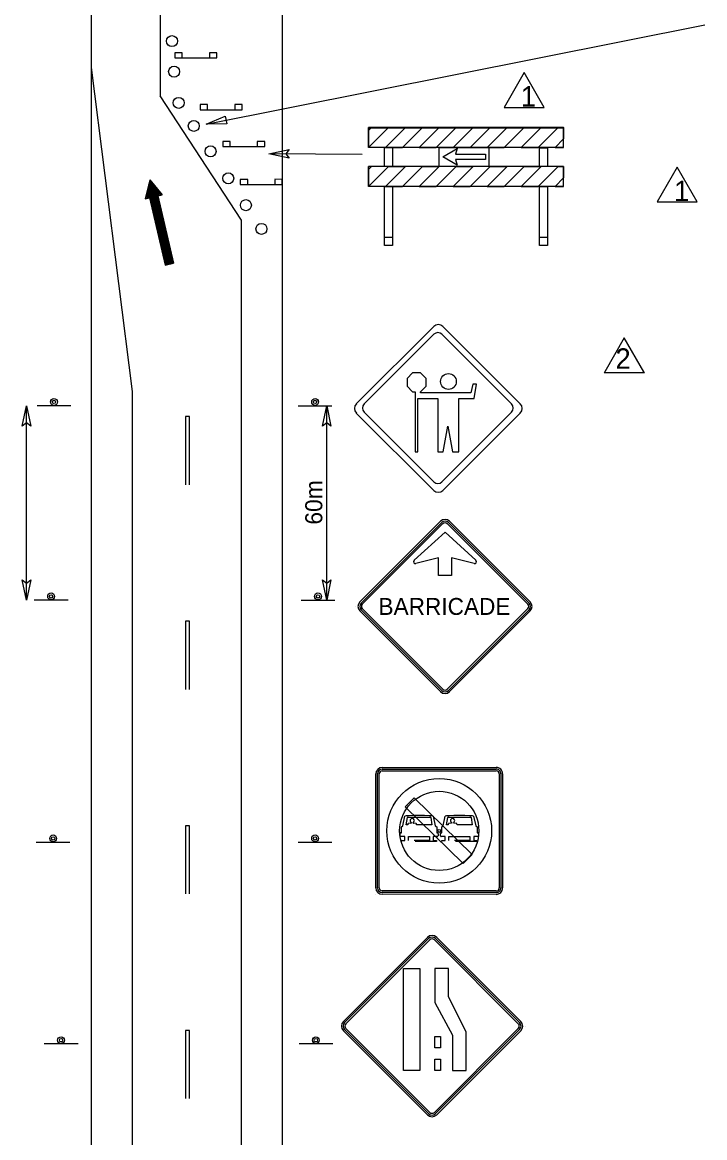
# Model space of a CAD drawing. Extents: x 1056 to 1280, y 240 to 519.
# Drawn here: x 1109.1 to 1157.5, y 308.9 to 388 of the extents above; entities that cross this region are included whole.
import ezdxf

# ---------------------------------------------------------------- set-up
doc = ezdxf.new("R2010")
doc.units = 0
for name, color, linetype in [('Level 1', 7, 'Continuous'), ('Level 10', 7, 'Continuous'), ('Level 17', 7, 'Continuous'), ('Level 29', 7, 'Continuous'), ('Level 44', 7, 'Continuous'), ('Level 5', 7, 'Continuous'), ('Level 60', 7, 'Continuous')]:
    doc.layers.add(name, color=color, linetype=linetype)

# ---------------------------------------------------------------- blocks, each defined once
blk = doc.blocks.new('LT1')
at = {"layer": 'Level 5'}
blk.add_lwpolyline([(0, 0), (-3, -0.62), (-2.504, 0), (-3, 0.62)], close=True, dxfattribs=at)

msp = doc.modelspace()

# ---------------------------------------------------------------- linework, layer by layer
at = {"layer": 'Level 1'}
for p, q in [((1136.814, 363.179), (1136.42, 362.785)), ((1137.371, 363.179), (1136.814, 363.179)), ((1137.765, 362.785), (1137.371, 363.179)), ((1136.42, 362.785), (1136.42, 362.228)), ((1137.765, 362.228), (1137.765, 362.785)), ((1141.085, 362.36), (1140.941, 361.761)), ((1141.335, 362.36), (1141.085, 362.36)), ((1141.172, 361.359), (1141.335, 362.36)), ((1136.42, 362.228), (1136.814, 361.834)), ((1136.814, 361.834), (1136.992, 361.834)), ((1136.992, 361.834), (1136.992, 357.568)), ((1137.371, 361.834), (1137.765, 362.228)), ((1137.371, 361.761), (1137.371, 361.834)), ((1140.941, 361.761), (1137.371, 361.761)), ((1137.188, 357.568), (1137.188, 361.359)), ((1137.188, 361.359), (1138.608, 361.359)), ((1138.608, 361.359), (1138.608, 357.568)), ((1140.096, 357.568), (1140.096, 361.359)), ((1140.096, 361.359), (1141.172, 361.359)), ((1138.984, 357.568), (1139.321, 359.384)), ((1139.321, 359.384), (1139.638, 357.568)), ((1136.992, 357.568), (1137.188, 357.568)), ((1138.608, 357.568), (1138.984, 357.568)), ((1139.638, 357.568), (1140.096, 357.568))]:
    msp.add_line(p, q, dxfattribs=at)
msp.add_circle((1139.357, 362.56), 0.559, dxfattribs=at)
at = {"layer": 'Level 10'}
for p, q in [((1114.044, 384.845), (1114.044, 432.01)), ((1127.591, 329.087), (1127.591, 431.499)), ((1114.044, 384.845), (1114.044, 397.84)), ((1122.169, 380.825), (1157.533, 387.859)), ((1116.947, 361.854), (1114.044, 384.845)), ((1114.044, 303.068), (1114.044, 384.845)), ((1124.688, 374.012), (1118.903, 382.817)), ((1118.173, 376.861), (1117.851, 375.527)), ((1118.133, 376.694), (1119.479, 370.866)), ((1118.173, 376.861), (1119.553, 370.883)), ((1118.173, 376.861), (1119.046, 375.803)), ((1118.281, 376.728), (1119.627, 370.9)), ((1117.93, 375.861), (1118, 375.561)), ((1117.971, 376.027), (1118.075, 375.579)), ((1118.012, 376.194), (1119.254, 370.814)), ((1118.052, 376.36), (1119.328, 370.831)), ((1118.091, 376.527), (1119.402, 370.848)), ((1118.391, 376.596), (1119.702, 370.917)), ((1118.5, 376.463), (1119.777, 370.934)), ((1118.609, 376.332), (1119.851, 370.952)), ((1118.718, 376.2), (1118.822, 375.751)), ((1118.827, 376.068), (1118.897, 375.768)), ((1118.937, 375.935), (1118.972, 375.786)), ((1117.851, 375.527), (1118.15, 375.596)), ((1117.891, 375.693), (1117.926, 375.545)), ((1118.15, 375.596), (1119.254, 370.814)), ((1118.747, 375.735), (1119.046, 375.803)), ((1118.747, 375.735), (1119.851, 370.952)), ((1124.688, 303.086), (1124.688, 374.012)), ((1119.254, 370.814), (1119.851, 370.952)), ((1116.947, 303.073), (1116.947, 361.854)), ((1109.429, 347.05), (1109.429, 360.84)), ((1130.722, 347.05), (1130.722, 360.84)), ((1120.705, 360.074), (1120.705, 355.236)), ((1120.995, 360.074), (1120.705, 360.074)), ((1120.995, 355.236), (1120.995, 360.074)), ((1120.705, 345.56), (1120.705, 340.722)), ((1120.995, 345.56), (1120.705, 345.56)), ((1120.995, 340.722), (1120.995, 345.56)), ((1120.705, 331.046), (1120.705, 326.208)), ((1120.995, 331.046), (1120.705, 331.046)), ((1120.995, 326.208), (1120.995, 331.046)), ((1127.591, 253.496), (1127.591, 329.087)), ((1120.705, 316.532), (1120.705, 311.694)), ((1120.995, 316.532), (1120.705, 316.532)), ((1120.995, 311.694), (1120.995, 316.532))]:
    msp.add_line(p, q, dxfattribs=at)
msp.add_lwpolyline([(1123.634, 380.841), (1122.169, 380.825), (1123.529, 381.371)], close=True, dxfattribs=at)
at = {"layer": 'Level 17'}
for p, q in [((1133.073, 346.927), (1138.792, 352.646)), ((1133.158, 346.842), (1138.877, 352.562)), ((1133.243, 346.758), (1138.962, 352.477)), ((1139.267, 352.477), (1144.987, 346.758)), ((1139.352, 352.562), (1145.071, 346.842)), ((1139.437, 352.646), (1145.156, 346.927)), ((1137.051, 349.644), (1137.051, 349.644)), ((1137.051, 349.644), (1137.051, 349.644)), ((1137.051, 349.644), (1137.051, 349.644)), ((1132.751, 346.605), (1132.751, 346.605)), ((1138.792, 340.563), (1133.073, 346.282)), ((1138.877, 340.648), (1133.158, 346.367)), ((1138.962, 340.733), (1133.243, 346.452)), ((1144.987, 346.452), (1139.267, 340.733)), ((1145.071, 346.367), (1139.352, 340.648)), ((1145.156, 346.282), (1139.437, 340.563)), ((1134.202, 326.645), (1134.202, 334.724)), ((1134.322, 326.645), (1134.322, 334.724)), ((1134.442, 326.645), (1134.442, 334.724)), ((1134.659, 335.181), (1142.743, 335.185)), ((1134.659, 335.061), (1142.743, 335.065)), ((1134.659, 334.941), (1142.743, 334.946)), ((1142.961, 334.729), (1142.96, 326.639)), ((1143.081, 334.729), (1143.08, 326.639)), ((1143.201, 334.729), (1143.2, 326.639)), ((1136.117, 331.041), (1136.267, 331.723)), ((1136.359, 331.104), (1136.445, 331.627)), ((1136.484, 331.667), (1138.053, 331.667)), ((1138.1, 331.627), (1138.18, 331.104)), ((1138.272, 331.723), (1138.422, 331.041)), ((1138.983, 331.041), (1139.133, 331.723)), ((1139.225, 331.104), (1139.311, 331.627)), ((1139.35, 331.667), (1140.919, 331.667)), ((1140.965, 331.627), (1141.046, 331.104)), ((1141.138, 331.723), (1141.288, 331.041)), ((1136.015, 330.971), (1136.118, 331.041)), ((1136.015, 330.552), (1136.015, 330.971)), ((1136.473, 331.104), (1136.359, 331.104)), ((1136.48, 331.173), (1136.473, 331.104)), ((1136.699, 331.224), (1136.526, 331.213)), ((1136.71, 331.287), (1136.71, 331.235)), ((1136.86, 331.235), (1136.86, 331.287)), ((1137.049, 331.213), (1136.876, 331.224)), ((1137.099, 331.104), (1137.088, 331.173)), ((1138.18, 331.104), (1137.099, 331.104)), ((1138.422, 331.041), (1138.525, 330.971)), ((1138.525, 330.971), (1138.525, 330.552)), ((1138.881, 330.971), (1138.984, 331.041)), ((1138.881, 330.552), (1138.881, 330.971)), ((1139.339, 331.104), (1139.225, 331.104)), ((1139.345, 331.173), (1139.339, 331.104)), ((1139.565, 331.224), (1139.392, 331.213)), ((1139.575, 331.287), (1139.575, 331.235)), ((1139.725, 331.235), (1139.725, 331.287)), ((1139.914, 331.213), (1139.742, 331.224)), ((1139.965, 331.104), (1139.954, 331.173)), ((1141.046, 331.104), (1139.965, 331.104)), ((1141.288, 331.041), (1141.39, 330.971)), ((1141.39, 330.971), (1141.39, 330.552)), ((1135.924, 330.329), (1135.924, 330.506)), ((1135.97, 330.552), (1136.015, 330.552)), ((1136.257, 330.282), (1135.97, 330.282)), ((1136.033, 329.937), (1136.033, 330.012)), ((1136.033, 330.012), (1136.257, 330.012)), ((1136.257, 330.012), (1136.257, 330.282)), ((1136.522, 330.012), (1136.522, 330.282)), ((1136.522, 330.282), (1138.019, 330.282)), ((1138.019, 330.012), (1136.922, 330.012)), ((1138.507, 329.937), (1136.997, 329.937)), ((1138.019, 330.282), (1138.019, 330.012)), ((1138.57, 330.282), (1138.283, 330.282)), ((1138.283, 330.282), (1138.283, 330.012)), ((1138.283, 330.012), (1138.507, 330.012)), ((1138.507, 330.012), (1138.507, 329.937)), ((1138.525, 330.552), (1138.57, 330.552)), ((1138.616, 330.506), (1138.616, 330.329)), ((1138.789, 330.329), (1138.789, 330.506)), ((1138.836, 330.552), (1138.881, 330.552)), ((1139.123, 330.282), (1138.836, 330.282)), ((1138.898, 329.937), (1138.898, 330.012)), ((1138.898, 330.012), (1139.123, 330.012)), ((1139.123, 330.012), (1139.123, 330.282)), ((1139.387, 330.012), (1139.387, 330.282)), ((1139.387, 330.282), (1140.884, 330.282)), ((1140.884, 330.012), (1139.788, 330.012)), ((1141.373, 329.937), (1139.862, 329.937)), ((1140.884, 330.282), (1140.884, 330.012)), ((1141.436, 330.282), (1141.149, 330.282)), ((1141.149, 330.282), (1141.149, 330.012)), ((1141.149, 330.012), (1141.373, 330.012)), ((1141.373, 330.012), (1141.373, 329.937)), ((1141.39, 330.552), (1141.436, 330.552)), ((1141.482, 330.506), (1141.482, 330.329)), ((1134.202, 326.189), (1134.202, 326.189)), ((1134.202, 326.189), (1134.202, 326.189)), ((1142.744, 326.423), (1134.659, 326.428)), ((1142.744, 326.303), (1134.659, 326.308)), ((1142.744, 326.183), (1134.659, 326.188)), ((1131.903, 317.172), (1137.861, 323.13)), ((1131.992, 317.083), (1137.95, 323.041)), ((1132.081, 316.996), (1138.039, 322.952)), ((1138.356, 322.952), (1144.313, 316.996)), ((1138.445, 323.041), (1144.402, 317.083)), ((1138.533, 323.13), (1144.491, 317.172)), ((1137.861, 310.543), (1131.903, 316.501)), ((1137.95, 310.631), (1131.992, 316.588)), ((1138.039, 310.72), (1132.081, 316.677)), ((1144.313, 316.677), (1138.356, 310.72)), ((1144.402, 316.588), (1138.445, 310.631)), ((1144.491, 316.501), (1138.533, 310.543)), ((1144.826, 316.836), (1144.826, 316.836))]:
    msp.add_line(p, q, dxfattribs=at)
for points in [[(1136.928, 349.878), (1139.115, 351.866), (1141.302, 349.878)], [(1136.928, 349.878), (1139.115, 351.866), (1141.302, 349.878)], [(1136.928, 349.878), (1139.115, 351.866), (1141.302, 349.878)], [(1141.173, 349.644), (1139.566, 350.056), (1139.566, 348.806), (1138.659, 348.806), (1138.659, 350.056), (1137.051, 349.644)], [(1141.173, 349.644), (1139.566, 350.056), (1139.566, 348.806), (1138.659, 348.806), (1138.659, 350.056), (1137.051, 349.644)], [(1141.173, 349.644), (1139.566, 350.056), (1139.566, 348.806), (1138.659, 348.806), (1138.659, 350.056), (1137.051, 349.644)]]:
    msp.add_lwpolyline(points, dxfattribs=at)
for points in [[(1136.93, 333.029), (1141.029, 329.004), (1140.394, 328.368), (1136.296, 332.393)], [(1136.157, 320.928), (1137.329, 320.928), (1137.329, 313.688), (1136.157, 313.688)], [(1138.383, 320.928), (1138.399, 318.517), (1139.647, 316.193), (1139.647, 313.688), (1140.622, 313.688), (1140.622, 316.433), (1139.357, 318.907), (1139.357, 320.928)], [(1138.399, 316.098), (1138.789, 316.098), (1138.789, 315.296), (1138.399, 315.296)], [(1138.399, 314.492), (1138.789, 314.492), (1138.789, 313.688), (1138.399, 313.688)]]:
    msp.add_lwpolyline(points, close=True, dxfattribs=at)
for radius in [3.715, 2.811, 0.109]:
    msp.add_circle((1138.703, 330.685), radius, dxfattribs=at)
for centre, radius, start, end in [((1139.115, 352.323), 0.456, 45, 135), ((1139.115, 352.323), 0.336, 45, 135), ((1139.115, 352.323), 0.216, 45, 135), ((1137.019, 349.774), 0.137, 132.30479, 284.40748), ((1137.019, 349.774), 0.137, 132.30479, 284.40748), ((1137.019, 349.774), 0.137, 132.30479, 284.40748), ((1141.208, 349.774), 0.137, 255.59252, 47.69521), ((1141.208, 349.774), 0.137, 255.59252, 47.69521), ((1141.208, 349.774), 0.137, 255.59252, 47.69521), ((1133.396, 346.604), 0.456, 135, 225), ((1133.396, 346.604), 0.336, 135, 225), ((1133.396, 346.604), 0.216, 135, 225), ((1144.834, 346.604), 0.216, 315, 45), ((1144.834, 346.604), 0.336, 315, 45), ((1144.834, 346.604), 0.456, 315, 45), ((1139.115, 340.885), 0.456, 225, 315), ((1139.115, 340.885), 0.336, 225, 315), ((1139.115, 340.885), 0.216, 225, 315), ((1134.66, 334.724), 0.457, 90.03529, 179.99948), ((1134.66, 334.724), 0.337, 90.03529, 179.99948), ((1134.66, 334.724), 0.217, 90.03529, 179.99948), ((1142.744, 334.729), 0.457, 0, 90.03486), ((1142.744, 334.729), 0.337, 0, 90.03486), ((1142.744, 334.729), 0.217, 0, 90.03486), ((1136.487, 331.62), 0.0448, 90, 170.90972), ((1136.788, 331.424), 0.149, 302.76657, 235.94147), ((1138.054, 331.62), 0.0448, 9.09028, 90), ((1139.353, 331.62), 0.0448, 90, 170.90972), ((1139.654, 331.424), 0.149, 302.76657, 235.94147), ((1140.92, 331.62), 0.0448, 9.09028, 90), ((1136.527, 331.167), 0.0448, 93.82218, 171.86989), ((1136.697, 331.238), 0.0149, 273.79849, 0), ((1136.697, 331.287), 0.015, 0, 60.10537), ((1136.876, 331.285), 0.0149, 119.13929, 180), ((1136.876, 331.238), 0.0149, 180, 266.20151), ((1137.046, 331.167), 0.0448, 8.11866, 86.21836), ((1139.393, 331.167), 0.0448, 93.82218, 171.86989), ((1139.563, 331.238), 0.0149, 273.79849, 0), ((1139.563, 331.287), 0.015, 0, 60.10537), ((1139.742, 331.285), 0.0149, 119.13929, 180), ((1139.742, 331.238), 0.0149, 180, 266.20151), ((1139.912, 331.167), 0.0448, 8.11866, 86.21836), ((1135.971, 330.508), 0.0448, 90.00001, 180.00001), ((1135.971, 330.328), 0.0448, 180.00001, 270), ((1138.57, 330.508), 0.0448, 359.99999, 89.99999), ((1138.57, 330.328), 0.0448, 270, 359.99999), ((1138.837, 330.508), 0.0448, 90.00001, 180.00001), ((1138.837, 330.328), 0.0448, 180.00001, 270), ((1141.436, 330.508), 0.0448, 359.99999, 89.99999), ((1141.436, 330.328), 0.0448, 270, 359.99999), ((1134.66, 326.645), 0.457, 180, 269.96489), ((1134.66, 326.645), 0.337, 180, 269.96489), ((1134.66, 326.645), 0.217, 180, 269.96489), ((1142.744, 326.64), 0.457, 269.96512, 0), ((1142.744, 326.64), 0.337, 269.96512, 0), ((1142.744, 326.64), 0.217, 269.96512, 0), ((1138.197, 322.793), 0.475, 45, 135), ((1138.197, 322.793), 0.35, 45, 135), ((1138.197, 322.793), 0.225, 45, 135), ((1132.239, 316.836), 0.475, 135, 225), ((1132.239, 316.836), 0.35, 135, 225), ((1132.239, 316.836), 0.225, 135, 225), ((1144.154, 316.836), 0.225, 315, 45), ((1144.154, 316.836), 0.35, 315, 45), ((1144.154, 316.836), 0.475, 315, 45), ((1138.197, 310.879), 0.475, 225, 315), ((1138.197, 310.879), 0.35, 225, 315), ((1138.197, 310.879), 0.225, 225, 315)]:
    msp.add_arc(centre, radius, start, end, dxfattribs=at)
for centre in [(1137.271, 331.725), (1140.136, 331.725)]:
    msp.add_ellipse(centre, major_axis=(-1.001, 0), ratio=0.04642, start_param=3.141593, end_param=6.283185, dxfattribs=at)
at = {"layer": 'Level 29'}
for points in [[(1151.832, 365.664), (1150.439, 363.239)], [(1153.226, 363.239), (1151.832, 365.664)], [(1150.439, 363.239), (1150.413, 363.194), (1153.252, 363.194), (1153.226, 363.239)]]:
    msp.add_lwpolyline(points, dxfattribs=at)
at = {"layer": 'Level 44'}
for p, q in [((1138.315, 366.462), (1132.821, 360.976)), ((1144.449, 360.976), (1138.965, 366.462)), ((1133.371, 360.972), (1138.315, 365.91)), ((1138.899, 365.91), (1143.837, 360.972)), ((1112.577, 360.84), (1110.181, 360.84)), ((1128.694, 360.84), (1131.09, 360.84)), ((1132.821, 360.326), (1138.315, 354.834)), ((1132.827, 360.326), (1132.821, 360.326)), ((1138.315, 355.446), (1133.371, 360.386)), ((1143.837, 360.386), (1138.899, 355.446)), ((1138.965, 354.834), (1144.449, 360.326)), ((1112.373, 347.05), (1109.976, 347.05)), ((1128.898, 347.05), (1131.294, 347.05)), ((1110.113, 329.884), (1112.509, 329.884)), ((1128.694, 329.884), (1131.09, 329.884)), ((1113.082, 315.572), (1110.686, 315.572)), ((1131.153, 315.572), (1128.757, 315.572))]:
    msp.add_line(p, q, dxfattribs=at)
for centre, radius in [((1111.374, 361.109), 0.24), ((1111.374, 361.109), 0.12), ((1129.897, 361.109), 0.24), ((1129.897, 361.109), 0.12), ((1111.169, 347.319), 0.24), ((1111.169, 347.319), 0.12), ((1130.102, 347.319), 0.24), ((1130.102, 347.319), 0.12), ((1111.317, 330.153), 0.24), ((1111.317, 330.153), 0.12), ((1129.897, 330.153), 0.24), ((1129.897, 330.153), 0.12), ((1111.877, 315.841), 0.24), ((1111.877, 315.841), 0.12), ((1129.949, 315.841), 0.24), ((1129.949, 315.841), 0.12)]:
    msp.add_circle(centre, radius, dxfattribs=at)
for centre, radius, start, end in [((1138.639, 366.139), 0.459, 45, 135), ((1138.606, 365.618), 0.413, 45, 135), ((1133.15, 360.65), 0.459, 135, 224.99999), ((1133.667, 360.678), 0.413, 135, 224.99999), ((1143.546, 360.678), 0.413, 315, 45), ((1144.127, 360.65), 0.459, 315, 45), ((1138.606, 355.739), 0.413, 225, 315), ((1138.639, 355.162), 0.459, 225, 315)]:
    msp.add_arc(centre, radius, start, end, dxfattribs=at)
at = {"layer": 'Level 5'}
for p, q in [((1118.931, 382.817), (1118.931, 459.29)), ((1120.47, 385.884), (1119.942, 385.884)), ((1119.942, 385.884), (1119.942, 385.514)), ((1119.942, 385.514), (1122.922, 385.515)), ((1120.47, 385.515), (1120.47, 385.884)), ((1122.922, 385.884), (1122.396, 385.885)), ((1122.396, 385.884), (1122.396, 385.515)), ((1122.922, 385.515), (1122.922, 385.884)), ((1122.274, 382.2), (1121.746, 382.2)), ((1121.746, 382.2), (1121.746, 381.829)), ((1122.274, 381.83), (1122.274, 382.2)), ((1124.726, 382.2), (1124.198, 382.201)), ((1124.198, 382.2), (1124.198, 381.829)), ((1124.726, 381.829), (1124.726, 382.2)), ((1121.746, 381.829), (1124.726, 381.829)), ((1147.523, 380.582), (1133.681, 380.582)), ((1133.681, 379.163), (1133.681, 380.582)), ((1146.388, 380.582), (1146.105, 380.582)), ((1147.523, 379.163), (1147.523, 380.582)), ((1147.538, 380.554), (1133.696, 380.554)), ((1133.696, 380.554), (1147.538, 380.554)), ((1134.831, 380.554), (1135.114, 380.554)), ((1146.404, 380.554), (1146.12, 380.554)), ((1123.874, 379.592), (1123.348, 379.592)), ((1123.348, 379.592), (1123.348, 379.222)), ((1123.348, 379.222), (1126.327, 379.222)), ((1123.874, 379.223), (1123.874, 379.592)), ((1126.327, 379.592), (1125.8, 379.594)), ((1125.8, 379.592), (1125.8, 379.222)), ((1126.327, 379.222), (1126.327, 379.592)), ((1147.523, 379.163), (1133.681, 379.163)), ((1134.816, 379.136), (1134.816, 379.163)), ((1138.734, 379.149), (1142.222, 379.149)), ((1138.734, 379.149), (1142.222, 379.149)), ((1145.821, 379.136), (1145.821, 379.163)), ((1133.228, 378.673), (1126.612, 378.707)), ((1133.681, 376.399), (1133.681, 377.817)), ((1147.523, 377.817), (1133.681, 377.817)), ((1146.388, 377.817), (1146.105, 377.817)), ((1147.523, 376.399), (1147.523, 377.817)), ((1125.115, 376.9), (1124.587, 376.9)), ((1124.587, 376.9), (1124.587, 376.528)), ((1125.115, 376.529), (1125.115, 376.9)), ((1127.568, 376.9), (1127.041, 376.901)), ((1127.041, 376.9), (1127.041, 376.529)), ((1127.568, 376.529), (1127.568, 376.9)), ((1124.587, 376.528), (1127.568, 376.529)), ((1147.523, 376.399), (1133.681, 376.399)), ((1135.383, 372.782), (1134.816, 372.782)), ((1146.388, 372.782), (1145.821, 372.782))]:
    msp.add_line(p, q, dxfattribs=at)
for points in [[(1133.681, 379.163), (1135.099, 380.582), (1133.896, 380.582), (1133.681, 380.367), (1133.681, 379.163)], [(1136.088, 379.163), (1137.506, 380.582), (1136.302, 380.582), (1134.884, 379.163), (1136.088, 379.163)], [(1138.495, 379.163), (1139.913, 380.582), (1138.709, 380.582), (1137.291, 379.163), (1138.495, 379.163)], [(1140.901, 379.163), (1142.319, 380.582), (1141.116, 380.582), (1139.698, 379.163), (1140.901, 379.163)], [(1144.726, 380.582), (1143.523, 380.582), (1142.105, 379.163), (1143.308, 379.163), (1144.726, 380.582)], [(1147.133, 380.582), (1145.931, 380.582), (1144.512, 379.163), (1145.716, 379.163), (1147.133, 380.582)], [(1147.523, 379.769), (1146.918, 379.163), (1147.523, 379.163), (1147.523, 379.769)], [(1133.681, 376.399), (1135.099, 377.817), (1133.896, 377.817), (1133.681, 377.602), (1133.681, 376.399)], [(1136.088, 376.399), (1137.506, 377.817), (1136.302, 377.817), (1134.884, 376.399), (1136.088, 376.399)], [(1138.495, 376.399), (1139.913, 377.817), (1138.709, 377.817), (1137.291, 376.399), (1138.495, 376.399)], [(1140.901, 376.399), (1142.319, 377.817), (1141.116, 377.817), (1139.698, 376.399), (1140.901, 376.399)], [(1144.726, 377.817), (1143.523, 377.817), (1142.105, 376.399), (1143.308, 376.399), (1144.726, 377.817)], [(1147.133, 377.817), (1145.931, 377.817), (1144.512, 376.399), (1145.716, 376.399), (1147.133, 377.817)], [(1147.523, 377.003), (1146.918, 376.399), (1147.523, 376.399), (1147.523, 377.003)]]:
    msp.add_lwpolyline(points, dxfattribs=at)
for points in [[(1135.099, 380.582), (1136.302, 380.582), (1134.884, 379.163), (1133.681, 379.163)], [(1133.896, 380.582), (1133.681, 380.582), (1133.681, 380.367)], [(1137.506, 380.582), (1138.709, 380.582), (1137.291, 379.163), (1136.088, 379.163)], [(1139.913, 380.582), (1141.116, 380.582), (1139.698, 379.163), (1138.495, 379.163)], [(1142.319, 380.582), (1143.523, 380.582), (1142.105, 379.163), (1140.901, 379.163)], [(1144.726, 380.582), (1145.931, 380.582), (1144.512, 379.163), (1143.308, 379.163)], [(1147.133, 380.582), (1147.523, 380.582), (1147.523, 379.769), (1146.918, 379.163), (1145.716, 379.163)], [(1134.816, 379.136), (1135.383, 379.163), (1135.383, 377.817), (1134.816, 377.817)], [(1142.222, 379.149), (1142.222, 377.817), (1138.709, 377.817), (1138.709, 379.149)], [(1141.995, 378.684), (1141.995, 378.31), (1139.868, 378.31), (1139.982, 377.912), (1138.961, 378.497), (1139.982, 379.081), (1139.868, 378.684)], [(1145.821, 379.136), (1146.388, 379.136), (1146.388, 377.817), (1145.821, 377.817)], [(1133.681, 377.817), (1133.896, 377.817), (1133.681, 377.602)], [(1135.099, 377.817), (1136.302, 377.817), (1134.884, 376.399), (1133.681, 376.399)], [(1137.506, 377.817), (1138.709, 377.817), (1137.291, 376.399), (1136.088, 376.399)], [(1139.913, 377.817), (1141.116, 377.817), (1139.698, 376.399), (1138.495, 376.399)], [(1142.319, 377.817), (1143.523, 377.817), (1142.105, 376.399), (1140.901, 376.399)], [(1144.726, 377.817), (1145.931, 377.817), (1144.512, 376.399), (1143.308, 376.399)], [(1147.133, 377.817), (1147.523, 377.817), (1147.523, 377.003), (1146.918, 376.399), (1145.716, 376.399)], [(1134.816, 376.384), (1135.383, 376.384), (1135.383, 372.214), (1134.816, 372.214)], [(1145.821, 376.384), (1146.388, 376.384), (1146.388, 372.214), (1145.821, 372.214)]]:
    msp.add_lwpolyline(points, close=True, dxfattribs=at)
for centre in [(1119.744, 386.705), (1119.899, 384.543), (1120.221, 382.326), (1121.295, 380.69), (1122.482, 378.884), (1123.736, 376.976), (1124.989, 375.069), (1126.093, 373.388)]:
    msp.add_circle(centre, 0.391, dxfattribs=at)
at = {"layer": 'Level 60'}
for points in [[(1144.72, 384.477), (1143.301, 382.007), (1146.139, 382.007)], [(1155.587, 377.768), (1154.168, 375.298), (1157.006, 375.298)]]:
    msp.add_lwpolyline(points, close=True, dxfattribs=at)

# ---------------------------------------------------------------- block references
at = {"layer": 'Level 5', "xscale": 0.4838}
for p, yscale, rotation in [((1126.612, 378.707), 0.48379999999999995, -179.86721270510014), ((1109.429, 360.84), 0.4838, 90), ((1130.722, 360.84), 0.4838, 90), ((1109.429, 347.05), 0.4838, -90), ((1130.722, 347.05), 0.4838, -90)]:
    msp.add_blockref('LT1', p, dxfattribs=dict(at, yscale=yscale, rotation=rotation))

# ---------------------------------------------------------------- texts
at = {"layer": 'Level 10'}
msp.add_text('2', height=1.448, rotation=360, dxfattribs=at).set_placement((1151.205, 363.463))
at = {"layer": 'Level 17'}
msp.add_text('BARRICADE', height=1.2, dxfattribs=at).set_placement((1134.393, 346.005))
at = {"layer": 'Level 44'}
msp.add_text('60m', height=1.2095, rotation=90, dxfattribs=at).set_placement((1130.409, 352.408))
at = {"layer": 'Level 60'}
for p in [(1144.493, 382.064), (1155.36, 375.355)]:
    msp.add_text('1', height=1.448, rotation=360, dxfattribs=at).set_placement(p)

doc.saveas('drawing.dxf')
